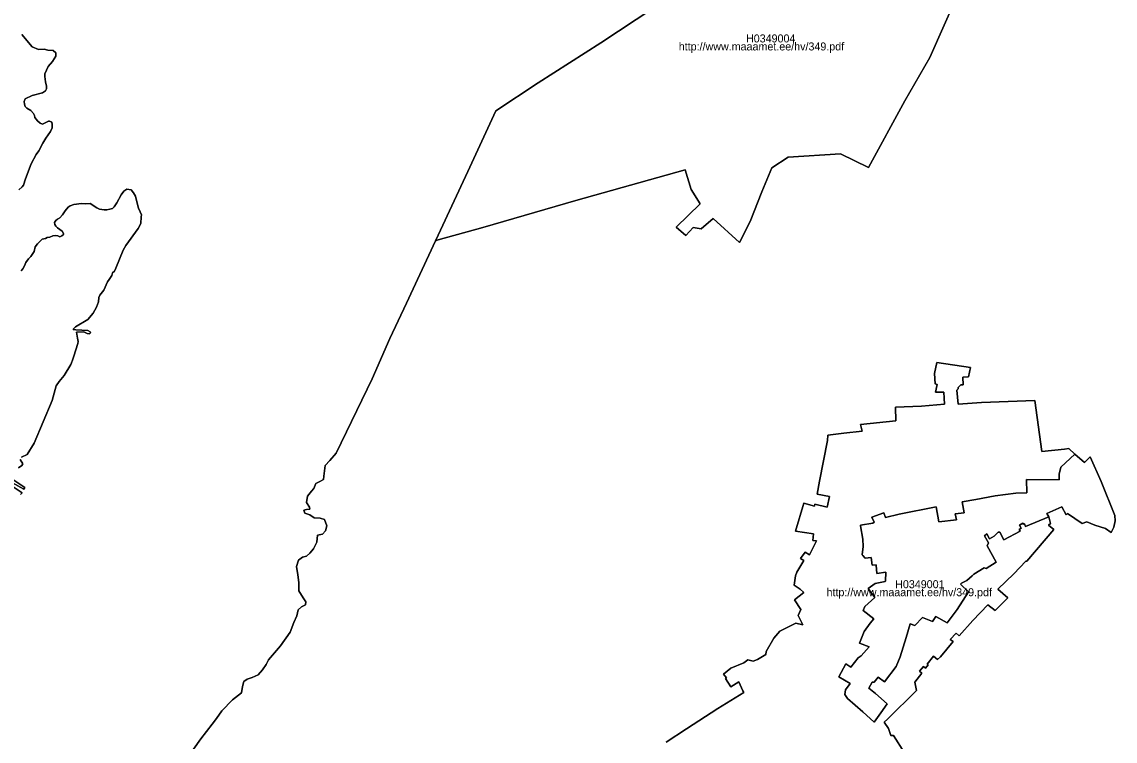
# Model space of a CAD drawing. Extents: x 369010 to 739155, y 6377141 to 6634081.
# Drawn here: x 408268 to 411682, y 6457361 to 6459609 of the extents above; entities that cross this region are included whole.
import ezdxf

# ---------------------------------------------------------------- set-up
doc = ezdxf.new("R2010")
doc.units = 0
for name, color, linetype in [('H_LINK', 7, 'Continuous'), ('H_PIIR', 7, 'Continuous'), ('H_TUNNUS', 7, 'Continuous')]:
    doc.layers.add(name, color=color, linetype=linetype)

msp = doc.modelspace()

# ---------------------------------------------------------------- linework, layer by layer
at = {"layer": 'H_PIIR'}
for points in [[(410406.5801, 6459763.3447), (410075.63, 6459543.3546), (409879.88, 6459418.1246), (409748, 6459331.1447), (409660.4299, 6459141.0446), (409567.4599, 6458942.0746), (409559.4256, 6458924.7699), (409468.9101, 6458729.8146), (409417.27, 6458619.5746), (409361.2, 6458493.5847), (409249.6301, 6458260.8146), (409229.16, 6458237.7446), (409215.22, 6458222.0646), (409210.8699, 6458188.9846), (409209.56, 6458178.9747), (409197.88, 6458172.2546), (409186.1199, 6458166.1546), (409179.59, 6458150.4846), (409171.7501, 6458141.7746), (409159.5499, 6458126.1046), (409156.5, 6458106.9547), (409165.65, 6458092.1446), (409167.39, 6458085.6147), (409156.5, 6458084.7446), (409147.86, 6458082.2746), (409150.9099, 6458073.1346), (409167.46, 6458068.3447), (409180.09, 6458058.3347), (409199.69, 6458057.4646), (409212.32, 6458053.9746), (409219.7201, 6458033.9546), (409215.8, 6458018.2846), (409206.22, 6458007.3946), (409190.98, 6458004.7847), (409188.3599, 6457983.0146), (409177.9799, 6457961.5047), (409167.0999, 6457948.0046), (409156.6399, 6457938.4247), (409144.0099, 6457935.8146), (409131.3801, 6457926.6746), (409125.72, 6457906.2147), (409129.21, 6457880.9646), (409132.26, 6457856.3146), (409132.26, 6457830.1946), (409146.19, 6457808.8646), (409154.4701, 6457796.4547), (409153.1599, 6457786.4446), (409140.5299, 6457780.3447), (409130.0799, 6457771.6447), (409126.1601, 6457752.4846), (409117.4499, 6457731.5946), (409105.25, 6457701.5546), (409075.4001, 6457658.7446), (409037.8299, 6457614.7447), (409030.2, 6457600.0946), (409018.8099, 6457583.8746), (409005.22, 6457567.6646), (408986.9, 6457559.4247), (408971.5601, 6457554.1647), (408961.0399, 6457547.5946), (408956.65, 6457531.3746), (408953.25, 6457512.1746), (408944.4801, 6457504.7246), (408925.19, 6457490.2546), (408892.4199, 6457455.7546), (408875.32, 6457431.2147), (408861.73, 6457414.1246), (408826.44, 6457367.8147), (408803.21, 6457335.3847)], [(411197.3, 6459709.72), (411103.07, 6459497.49), (411025.15, 6459361.86), (410911.8699, 6459153.23), (410824.0899, 6459196.29), (410660.8, 6459185.7701), (410609.77, 6459152.2701), (410579.15, 6459077.62), (410542.41, 6458984.7899), (410508.87, 6458918.81), (410427.2199, 6458994.42), (410389.46, 6458961.8801), (410363.94, 6458965.71), (410341.49, 6458940.83), (410310.87, 6458966.67), (410386.47, 6459040.2199), (410358.19, 6459084.6699), (410339.4599, 6459146.68), (409997.68, 6459050.86), (409707.46, 6458966.09), (409568.0599, 6458927.1799), (409559.4256, 6458924.7699), (409567.4599, 6458942.0746), (409660.4299, 6459141.0446), (409748, 6459331.1447), (409879.88, 6459418.1246), (410075.63, 6459543.3546), (410406.5801, 6459763.3447)], [(408803.21, 6457335.3847), (408826.44, 6457367.8147), (408861.73, 6457414.1246), (408875.32, 6457431.2147), (408892.4199, 6457455.7546), (408925.19, 6457490.2546), (408944.4801, 6457504.7246), (408953.25, 6457512.1746), (408956.65, 6457531.3746), (408961.0399, 6457547.5946), (408971.5601, 6457554.1647), (408986.9, 6457559.4247), (409005.22, 6457567.6646), (409018.8099, 6457583.8746), (409030.2, 6457600.0946), (409037.8299, 6457614.7447), (409075.4001, 6457658.7446), (409105.25, 6457701.5546), (409117.4499, 6457731.5946), (409126.1601, 6457752.4846), (409130.0799, 6457771.6447), (409140.5299, 6457780.3447), (409153.1599, 6457786.4446), (409154.4701, 6457796.4547), (409146.19, 6457808.8646), (409132.26, 6457830.1946), (409132.26, 6457856.3146), (409129.21, 6457880.9646), (409125.72, 6457906.2147), (409131.3801, 6457926.6746), (409144.0099, 6457935.8146), (409156.6399, 6457938.4247), (409167.0999, 6457948.0046), (409177.9799, 6457961.5047), (409188.3599, 6457983.0146), (409190.98, 6458004.7847), (409206.22, 6458007.3946), (409215.8, 6458018.2846), (409219.7201, 6458033.9546), (409212.32, 6458053.9746), (409199.69, 6458057.4646), (409180.09, 6458058.3347), (409167.46, 6458068.3447), (409150.9099, 6458073.1346), (409147.86, 6458082.2746), (409156.5, 6458084.7446), (409167.39, 6458085.6147), (409165.65, 6458092.1446), (409156.5, 6458106.9547), (409159.5499, 6458126.1046), (409171.7501, 6458141.7746), (409179.59, 6458150.4846), (409186.1199, 6458166.1546), (409197.88, 6458172.2546), (409209.56, 6458178.9747), (409210.8699, 6458188.9846), (409215.22, 6458222.0646), (409229.16, 6458237.7446), (409249.6301, 6458260.8146), (409361.2, 6458493.5847), (409417.27, 6458619.5746), (409468.9101, 6458729.8146), (409559.4256, 6458924.7699), (409568.0599, 6458927.1799), (409707.46, 6458966.09), (409997.68, 6459050.86), (410339.4599, 6459146.68), (410358.19, 6459084.6699), (410386.47, 6459040.2199), (410310.87, 6458966.67), (410341.49, 6458940.83), (410363.94, 6458965.71), (410389.46, 6458961.8801), (410427.2199, 6458994.42), (410508.87, 6458918.81), (410542.41, 6458984.7899), (410579.15, 6459077.62), (410609.77, 6459152.2701), (410660.8, 6459185.7701), (410824.0899, 6459196.29), (410911.8699, 6459153.23), (411025.15, 6459361.86), (411103.07, 6459497.49), (411197.3, 6459709.72)], [(408258.3099, 6459083.87), (408268.6399, 6459092.7199), (408272.3301, 6459097.8799), (408278.98, 6459118.52), (408296.69, 6459165.25), (408312.18, 6459194), (408320.3, 6459205.7899), (408332.8501, 6459229.38), (408342.42, 6459245.1401), (408357.2, 6459266.5301), (408362.37, 6459277.59), (408362.37, 6459287.9101), (408360.89, 6459295.2799), (408354.2501, 6459298.2301), (408350.56, 6459298.2301), (408332.1099, 6459288.65), (408324.7301, 6459292.3299), (408316.6099, 6459299.71), (408308.4899, 6459310.03), (408307.02, 6459315.92), (408304.0701, 6459322.56), (408295.9501, 6459332.1399), (408283.4, 6459338.78), (408278.24, 6459344.67), (408275.29, 6459351.3101), (408274.5501, 6459359.4201), (408278.24, 6459368.26), (408299.64, 6459378.14), (408332.1099, 6459386.9799), (408340.9701, 6459392.8801), (408344.66, 6459399.51), (408344.66, 6459407.62), (408341.7, 6459421.6299), (408339.49, 6459437.8501), (408339.49, 6459446.69), (408349.82, 6459468.81), (408363.17, 6459484.86), (408373.63, 6459501.12), (408373.1899, 6459511.97), (408365.39, 6459519.1299), (408348.8999, 6459519.7801), (408336.98, 6459523.47), (408318.9701, 6459522.6099), (408300.11, 6459530.42), (408267.19, 6459568.93)], [(408267.19, 6459568.93), (408300.11, 6459530.42), (408318.9701, 6459522.6099), (408336.98, 6459523.47), (408348.8999, 6459519.7801), (408365.39, 6459519.1299), (408373.1899, 6459511.97), (408373.63, 6459501.12), (408363.17, 6459484.86), (408349.82, 6459468.81), (408339.49, 6459446.69), (408339.49, 6459437.8501), (408341.7, 6459421.6299), (408344.66, 6459407.62), (408344.66, 6459399.51), (408340.9701, 6459392.8801), (408332.1099, 6459386.9799), (408299.64, 6459378.14), (408278.24, 6459368.26), (408274.5501, 6459359.4201), (408275.29, 6459351.3101), (408278.24, 6459344.67), (408283.4, 6459338.78), (408295.9501, 6459332.1399), (408304.0701, 6459322.56), (408307.02, 6459315.92), (408308.4899, 6459310.03), (408316.6099, 6459299.71), (408324.7301, 6459292.3299), (408332.1099, 6459288.65), (408350.56, 6459298.2301), (408354.2501, 6459298.2301), (408360.89, 6459295.2799), (408362.37, 6459287.9101), (408362.37, 6459277.59), (408357.2, 6459266.5301), (408342.42, 6459245.1401), (408332.8501, 6459229.38), (408320.3, 6459205.7899), (408312.18, 6459194), (408296.69, 6459165.25), (408278.98, 6459118.52), (408272.3301, 6459097.8799), (408268.6399, 6459092.7199), (408258.3099, 6459083.87)], [(408266.14, 6458248.28), (408284.3601, 6458256.0999), (408305.53, 6458291.52), (408362.36, 6458425.64), (408374.8799, 6458470.9201), (408383.99, 6458484.38), (408399.1701, 6458503.48), (408420.2, 6458537.61), (408422.3201, 6458543.0101), (408425.47, 6458550.9999), (408429.5, 6458563.88), (408442.72, 6458603.08), (408443.87, 6458609.7899), (408441.7599, 6458620.37), (408438.0443, 6458639.0012), (408461.32, 6458639.73), (408471.8499, 6458634.35), (408478.37, 6458633.5801), (408482.01, 6458636.4601), (408480.4799, 6458639.9201), (408473.2, 6458644.22), (408436.5813, 6458646.3368), (408427.5301, 6458646.8601), (408428.5099, 6458649.83), (408434.9299, 6458655.76), (408473.95, 6458678.4899), (408489.7501, 6458698.2501), (408501.11, 6458717.52), (408506.5401, 6458733.3299), (408507.5, 6458747.42), (408511.46, 6458754.83), (408523.8001, 6458770.1399), (408534.6699, 6458795.84), (408540.5901, 6458803.2501), (408548.4999, 6458816.1), (408550.47, 6458824.5001), (408556.4, 6458829.93), (408561.3401, 6458838.8299), (408584.05, 6458895.65), (408591.9501, 6458909.9801), (408630.4799, 6458962.85), (408639.37, 6458978.6601), (408640.3901, 6458999.57), (408640.8799, 6459005.1501), (408637.19, 6459015.4699), (408632.02, 6459026.5301), (408628.3301, 6459037.58), (408622.4299, 6459064.12), (408616.53, 6459074.4401), (408609.1499, 6459083.29), (408595.12, 6459086.24), (408586.27, 6459079.6001), (408577.4099, 6459068.5499), (408564.1299, 6459043.48), (408556.0099, 6459030.9499), (408550.11, 6459025.05), (408542.7299, 6459022.84), (408532.3999, 6459021.37), (408524.2799, 6459021.37), (408509.9601, 6459023.5801), (408501.8399, 6459027.26), (408480.4399, 6459040.53), (408466.42, 6459039.8001), (408453.8799, 6459040.53), (408430.2599, 6459037.58), (408418.45, 6459033.8999), (408412.55, 6459029.48), (408402.96, 6459018.4201), (408394.1, 6459005.89), (408385.9801, 6458996.3), (408378.6, 6458991.8801), (408373.44, 6458987.46), (408369.01, 6458981.56), (408370.48, 6458975.6599), (408373.44, 6458970.5001), (408378.6, 6458964.5999), (408393.3599, 6458955.02), (408397.05, 6458947.65), (408397.05, 6458943.9601), (408392.62, 6458939.54), (408385.9801, 6458936.59), (408379.34, 6458940.28), (408373.44, 6458941.0199), (408363.84, 6458939.54), (408354.99, 6458935.8601), (408346.1301, 6458935.12), (408340.9701, 6458931.43), (408330.63, 6458929.22), (408315.87, 6458914.4799), (408309.2301, 6458905.63), (408305.54, 6458890.8901), (408295.2099, 6458875.41), (408288.57, 6458868.04), (408279.7099, 6458856.2401), (408276.02, 6458846.66), (408270.86, 6458837.0799), (408265.69, 6458830.44)], [(408265.69, 6458830.44), (408270.86, 6458837.0799), (408276.02, 6458846.66), (408279.7099, 6458856.2401), (408288.57, 6458868.04), (408295.2099, 6458875.41), (408305.54, 6458890.8901), (408309.2301, 6458905.63), (408315.87, 6458914.4799), (408330.63, 6458929.22), (408340.9701, 6458931.43), (408346.1301, 6458935.12), (408354.99, 6458935.8601), (408363.84, 6458939.54), (408373.44, 6458941.0199), (408379.34, 6458940.28), (408385.9801, 6458936.59), (408392.62, 6458939.54), (408397.05, 6458943.9601), (408397.05, 6458947.65), (408393.3599, 6458955.02), (408378.6, 6458964.5999), (408373.44, 6458970.5001), (408370.48, 6458975.6599), (408369.01, 6458981.56), (408373.44, 6458987.46), (408378.6, 6458991.8801), (408385.9801, 6458996.3), (408394.1, 6459005.89), (408402.96, 6459018.4201), (408412.55, 6459029.48), (408418.45, 6459033.8999), (408430.2599, 6459037.58), (408453.8799, 6459040.53), (408466.42, 6459039.8001), (408480.4399, 6459040.53), (408501.8399, 6459027.26), (408509.9601, 6459023.5801), (408524.2799, 6459021.37), (408532.3999, 6459021.37), (408542.7299, 6459022.84), (408550.11, 6459025.05), (408556.0099, 6459030.9499), (408564.1299, 6459043.48), (408577.4099, 6459068.5499), (408586.27, 6459079.6001), (408595.12, 6459086.24), (408609.1499, 6459083.29), (408616.53, 6459074.4401), (408622.4299, 6459064.12), (408628.3301, 6459037.58), (408632.02, 6459026.5301), (408637.19, 6459015.4699), (408640.8799, 6459005.1501), (408640.3901, 6458999.57), (408639.37, 6458978.6601), (408630.4799, 6458962.85), (408591.9501, 6458909.9801), (408584.05, 6458895.65), (408561.3401, 6458838.8299), (408556.4, 6458829.93), (408550.47, 6458824.5001), (408548.4999, 6458816.1), (408540.5901, 6458803.2501), (408534.6699, 6458795.84), (408523.8001, 6458770.1399), (408511.46, 6458754.83), (408507.5, 6458747.42), (408506.5401, 6458733.3299), (408501.11, 6458717.52), (408489.7501, 6458698.2501), (408473.95, 6458678.4899), (408434.9299, 6458655.76), (408428.5099, 6458649.83), (408427.5301, 6458646.8601), (408436.5813, 6458646.3368), (408473.2, 6458644.22), (408480.4799, 6458639.9201), (408482.01, 6458636.4601), (408478.37, 6458633.5801), (408471.8499, 6458634.35), (408461.32, 6458639.73), (408438.0443, 6458639.0012), (408441.7599, 6458620.37), (408443.87, 6458609.7899), (408442.72, 6458603.08), (408429.5, 6458563.88), (408425.47, 6458550.9999), (408422.3201, 6458543.0101), (408420.2, 6458537.61), (408399.1701, 6458503.48), (408383.99, 6458484.38), (408374.8799, 6458470.9201), (408362.36, 6458425.64), (408305.53, 6458291.52), (408284.3601, 6458256.0999), (408266.14, 6458248.28)], [(411024.75, 6457323.99), (410989.9001, 6457378.37), (410982.15, 6457377.9899), (410974.41, 6457399.9701), (410961.16, 6457419.85), (410970.93, 6457429.59), (411061.8299, 6457519.19), (411056.55, 6457545.62), (411079.01, 6457572.71), (411071.7401, 6457579.3199), (411083.64, 6457593.8501), (411090.2501, 6457588.5699), (411098.1699, 6457599.14), (411095.06, 6457601.44), (411115.3, 6457626.6799), (411127.1199, 6457616.16), (411136.8499, 6457624.05), (411176.6999, 6457671.7501), (411167.24, 6457678.5899), (411185.3699, 6457698.04), (411195.36, 6457690.41), (411238.06, 6457737.3599), (411284.7201, 6457786.9799), (411308.05, 6457769.01), (411346.8, 6457808.85), (411315.55, 6457836.2001), (411365.4801, 6457883.59), (411402.8599, 6457923.3201), (411406.3699, 6457923.3201), (411491.05, 6458022.64), (411474.12, 6458035.49), (411479.96, 6458041.33), (411474.82, 6458061.33), (411468.99, 6458072.6599), (411515.65, 6458092.58), (411529.3901, 6458068.36), (411533.14, 6458072.27), (411579.8, 6458041.0101), (411593.55, 6458045.7), (411619.3801, 6458035.54), (411652.7099, 6458025.3901), (411669.3799, 6458012.89), (411678.1199, 6458029.29), (411682.2901, 6458049.22), (411681.46, 6458066.02), (411638.61, 6458171.79), (411604.44, 6458249.1399), (411586.53, 6458231.17), (411556.53, 6458257.74), (411537.62, 6458275.2301), (411523.82, 6458273.3799), (411453.1801, 6458265.9901), (411431.1599, 6458425.8801), (411265.0301, 6458418.71), (411191.6, 6458414.3801), (411188.3101, 6458457.5099), (411192.2599, 6458461.5199), (411192.2599, 6458465.5199), (411200.14, 6458474.1499), (411207.3701, 6458474.7699), (411206.7099, 6458498.4899), (411224.45, 6458499.41), (411231.0201, 6458528.37), (411124.9001, 6458544.0399), (411118.0001, 6458509.5401), (411119.6501, 6458477.1901), (411126.22, 6458475.65), (411121.62, 6458451.62), (411147.2399, 6458451.62), (411149.5399, 6458413.42), (411077.96, 6458407.8699), (410996.48, 6458404.3699), (410997.46, 6458361.59), (410887.2201, 6458350.37), (410891.8201, 6458329.72), (410834.5799, 6458323.1601), (410785.28, 6458317.13), (410783.8501, 6458299.9799), (410758.9299, 6458172.8), (410751.7, 6458132.44), (410790.47, 6458125.6599), (410782.5899, 6458091.7701), (410744.14, 6458101.6301), (410742.8299, 6458095.1599), (410709.65, 6458104.1), (410684.0501, 6458016.8001), (410740.5701, 6458008.48), (410737.94, 6457987.8399), (410749.1099, 6457986.91), (410728.08, 6457943.4701), (410713.62, 6457951.17), (410699.17, 6457931.77), (410710.34, 6457925.3), (410687.67, 6457889.38), (410683.73, 6457877.6801), (410679.79, 6457847.79), (410698.5101, 6457836.0899), (410709.69, 6457824.99), (410680.77, 6457801.89), (410700.49, 6457772.31), (410692.29, 6457753.0701), (410706.74, 6457724.7199), (410685.0599, 6457729.65), (410635.12, 6457705), (410616.3899, 6457682.82), (410592.52, 6457640.73), (410591.54, 6457631.49), (410565.2501, 6457615.7701), (410551.45, 6457610.84), (410535.35, 6457614.5399), (410522.5401, 6457605.61), (410481.4699, 6457589.2801), (410459.4599, 6457569.87), (410468.66, 6457558.78), (410465.7, 6457556.3101), (410482.46, 6457530.13), (410507.4299, 6457545.8399), (410519.5801, 6457518.1099), (410522.5401, 6457512.5601), (410441.43, 6457463.1), (410343.6301, 6457399.08), (410279.6101, 6457357.8401)], [(410279.6101, 6457357.8401), (410343.6301, 6457399.08), (410441.43, 6457463.1), (410522.5401, 6457512.5601), (410519.5801, 6457518.1099), (410507.4299, 6457545.8399), (410482.46, 6457530.13), (410465.7, 6457556.3101), (410468.66, 6457558.78), (410459.4599, 6457569.87), (410481.4699, 6457589.2801), (410522.5401, 6457605.61), (410535.35, 6457614.5399), (410551.45, 6457610.84), (410565.2501, 6457615.7701), (410591.54, 6457631.49), (410592.52, 6457640.73), (410616.3899, 6457682.82), (410635.12, 6457705), (410685.0599, 6457729.65), (410706.74, 6457724.7199), (410692.29, 6457753.0701), (410700.49, 6457772.31), (410680.77, 6457801.89), (410709.69, 6457824.99), (410698.5101, 6457836.0899), (410679.79, 6457847.79), (410683.73, 6457877.6801), (410687.67, 6457889.38), (410710.34, 6457925.3), (410699.17, 6457931.77), (410713.62, 6457951.17), (410728.08, 6457943.4701), (410749.1099, 6457986.91), (410737.94, 6457987.8399), (410740.5701, 6458008.48), (410684.0501, 6458016.8001), (410709.65, 6458104.1), (410742.8299, 6458095.1599), (410744.14, 6458101.6301), (410782.5899, 6458091.7701), (410790.47, 6458125.6599), (410751.7, 6458132.44), (410758.9299, 6458172.8), (410783.8501, 6458299.9799), (410785.28, 6458317.13), (410834.5799, 6458323.1601), (410891.8201, 6458329.72), (410887.2201, 6458350.37), (410997.46, 6458361.59), (410996.48, 6458404.3699), (411077.96, 6458407.8699), (411149.5399, 6458413.42), (411147.2399, 6458451.62), (411121.62, 6458451.62), (411126.22, 6458475.65), (411119.6501, 6458477.1901), (411118.0001, 6458509.5401), (411124.9001, 6458544.0399), (411231.0201, 6458528.37), (411224.45, 6458499.41), (411206.7099, 6458498.4899), (411207.3701, 6458474.7699), (411200.14, 6458474.1499), (411192.2599, 6458465.5199), (411192.2599, 6458461.5199), (411188.3101, 6458457.5099), (411191.6, 6458414.3801), (411265.0301, 6458418.71), (411431.1599, 6458425.8801), (411453.1801, 6458265.9901), (411523.82, 6458273.3799), (411537.62, 6458275.2301), (411556.53, 6458257.74), (411512.37, 6458216.72), (411507.79, 6458195.23), (411507.49, 6458177.0299), (411405.42, 6458178.59), (411406.26, 6458137.18), (411371.7901, 6458136.01), (411308.04, 6458127.0201), (411247.27, 6458116.16), (411204.78, 6458108.74), (411210.61, 6458074.3599), (411183.1201, 6458070.8399), (411186.4499, 6458052.4799), (411131.87, 6458045.84), (411123.54, 6458092.72), (411007.48, 6458069.62), (410965.4, 6458059.86), (410959.57, 6458073.9201), (410922.07, 6458061.0299), (410929.57, 6458044.62), (410925.41, 6458042.28), (410886.66, 6458036.03), (410886.9899, 6458033.9699), (410893.74, 6457992.27), (410895.41, 6457968.99), (410892.08, 6457942.8199), (410893.74, 6457941.0499), (410901.24, 6457933.0499), (410920.41, 6457935), (410920.4899, 6457934.35), (410923.3999, 6457910.4), (410935.4, 6457911.95), (410935.6501, 6457909.26), (410937.8299, 6457885.7601), (410937.9001, 6457885), (410966.2301, 6457888.51), (410965.4, 6457860.3901), (410964.16, 6457860.14), (410932.49, 6457853.75), (410910.47, 6457837.54), (410932.1401, 6457809.81), (410900.02, 6457781.19), (410895.47, 6457769.1799), (410928.8, 6457742.6099), (410917.1401, 6457729.3299), (410898.39, 6457703.55), (410883.39, 6457666.83), (410914.2401, 6457655.66), (410889.25, 6457627.54), (410879.25, 6457620.8999), (410856.75, 6457592.38), (410841.34, 6457602.14), (410819.6701, 6457561.91), (410855.08, 6457541.1999), (410839.6699, 6457521.28), (410837.5901, 6457506.82), (410846.7501, 6457494.32), (410893.83, 6457452.5201), (410929.2401, 6457419.71), (410950.38, 6457449.6401), (410970.0699, 6457477.52), (410934.2, 6457509.4899), (410912.74, 6457525.97), (410923.78, 6457544.7399), (410929.3001, 6457544.7399), (410941.9901, 6457560.75), (410961.67, 6457546.4599), (410998.27, 6457594.5), (411010.35, 6457624.58), (411029.1001, 6457684.74), (411041.9, 6457727.6499), (411056.9, 6457722.5701), (411081.0601, 6457747.1799), (411111.89, 6457734.29), (411121.8899, 6457750.6899), (411157.7201, 6457730.77), (411188.9001, 6457772.1301), (411224.31, 6457827.15), (411199.2199, 6457851), (411202.43, 6457854.1101), (411218.9001, 6457863.1699), (411235.6801, 6457877.44), (411240.56, 6457882.3001), (411273.48, 6457902.22), (411279.72, 6457899.88), (411310.42, 6457919.99), (411282.51, 6457971.55), (411286.68, 6457980.9299), (411274.1799, 6458002.8099), (411281.2601, 6458008.28), (411289.59, 6457993.43), (411304.59, 6458001.2401), (411317.09, 6458013.7399), (411322.51, 6458013.7399), (411334.1699, 6457990.3001), (411385.83, 6458016.87), (411382.0799, 6458022.73), (411389.1601, 6458026.25), (411383.3301, 6458036.01), (411394.1599, 6458041.87), (411395.83, 6458038.7501), (411399.16, 6458040.3099), (411401.91, 6458031.6399), (411474.82, 6458061.33), (411479.96, 6458041.33), (411474.12, 6458035.49), (411491.05, 6458022.64), (411406.3699, 6457923.3201), (411402.8599, 6457923.3201), (411365.4801, 6457883.59), (411315.55, 6457836.2001), (411346.8, 6457808.85), (411308.05, 6457769.01), (411284.7201, 6457786.9799), (411238.06, 6457737.3599), (411195.36, 6457690.41), (411185.3699, 6457698.04), (411167.24, 6457678.5899), (411176.6999, 6457671.7501), (411136.8499, 6457624.05), (411127.1199, 6457616.16), (411115.3, 6457626.6799), (411095.06, 6457601.44), (411098.1699, 6457599.14), (411090.2501, 6457588.5699), (411083.64, 6457593.8501), (411071.7401, 6457579.3199), (411079.01, 6457572.71), (411056.55, 6457545.62), (411061.8299, 6457519.19), (410970.93, 6457429.59), (410961.16, 6457419.85), (410974.41, 6457399.9701), (410982.15, 6457377.9899), (410989.9001, 6457378.37), (411024.75, 6457323.99)], [(408257.03, 6458215.3001), (408267.88, 6458222.6699), (408270.92, 6458227.8799), (408262.24, 6458240.9)], [(408262.24, 6458240.9), (408270.92, 6458227.8799), (408267.88, 6458222.6699), (408257.03, 6458215.3001)], [(408237.95, 6458167.9801), (408273.52, 6458148.02), (408276.99, 6458153.22), (408235.7799, 6458181)], [(408235.7799, 6458181), (408276.99, 6458153.22), (408273.52, 6458148.02), (408237.95, 6458167.9801)], [(408263.5399, 6458131.5199), (408268.7499, 6458136.7299), (408234.48, 6458159.3001)], [(408234.48, 6458159.3001), (408268.7499, 6458136.7299), (408263.5399, 6458131.5199)]]:
    msp.add_lwpolyline(points, dxfattribs=at)
msp.add_lwpolyline([(411556.53, 6458257.74), (411586.53, 6458231.17), (411604.44, 6458249.1399), (411638.61, 6458171.79), (411681.46, 6458066.02), (411682.2901, 6458049.22), (411678.1199, 6458029.29), (411669.3799, 6458012.89), (411652.7099, 6458025.3901), (411619.3801, 6458035.54), (411593.55, 6458045.7), (411579.8, 6458041.0101), (411533.14, 6458072.27), (411529.3901, 6458068.36), (411515.65, 6458092.58), (411468.99, 6458072.6599), (411474.82, 6458061.33), (411401.91, 6458031.6399), (411399.16, 6458040.3099), (411395.83, 6458038.7501), (411394.1599, 6458041.87), (411383.3301, 6458036.01), (411389.1601, 6458026.25), (411382.0799, 6458022.73), (411385.83, 6458016.87), (411334.1699, 6457990.3001), (411322.51, 6458013.7399), (411317.09, 6458013.7399), (411304.59, 6458001.2401), (411289.59, 6457993.43), (411281.2601, 6458008.28), (411274.1799, 6458002.8099), (411286.68, 6457980.9299), (411282.51, 6457971.55), (411310.42, 6457919.99), (411279.72, 6457899.88), (411273.48, 6457902.22), (411240.56, 6457882.3001), (411235.6801, 6457877.44), (411218.9001, 6457863.1699), (411202.43, 6457854.1101), (411199.2199, 6457851), (411224.31, 6457827.15), (411188.9001, 6457772.1301), (411157.7201, 6457730.77), (411121.8899, 6457750.6899), (411111.89, 6457734.29), (411081.0601, 6457747.1799), (411056.9, 6457722.5701), (411041.9, 6457727.6499), (411029.1001, 6457684.74), (411010.35, 6457624.58), (410998.27, 6457594.5), (410961.67, 6457546.4599), (410941.9901, 6457560.75), (410929.3001, 6457544.7399), (410923.78, 6457544.7399), (410912.74, 6457525.97), (410934.2, 6457509.4899), (410970.0699, 6457477.52), (410950.38, 6457449.6401), (410929.2401, 6457419.71), (410893.83, 6457452.5201), (410846.7501, 6457494.32), (410837.5901, 6457506.82), (410839.6699, 6457521.28), (410855.08, 6457541.1999), (410819.6701, 6457561.91), (410841.34, 6457602.14), (410856.75, 6457592.38), (410879.25, 6457620.8999), (410889.25, 6457627.54), (410914.2401, 6457655.66), (410883.39, 6457666.83), (410898.39, 6457703.55), (410917.1401, 6457729.3299), (410928.8, 6457742.6099), (410895.47, 6457769.1799), (410900.02, 6457781.19), (410932.1401, 6457809.81), (410910.47, 6457837.54), (410932.49, 6457853.75), (410964.16, 6457860.14), (410965.4, 6457860.3901), (410966.2301, 6457888.51), (410937.9001, 6457885), (410937.8299, 6457885.7601), (410935.6501, 6457909.26), (410935.4, 6457911.95), (410923.3999, 6457910.4), (410920.4899, 6457934.35), (410920.41, 6457935), (410901.24, 6457933.0499), (410893.74, 6457941.0499), (410892.08, 6457942.8199), (410895.41, 6457968.99), (410893.74, 6457992.27), (410886.9899, 6458033.9699), (410886.66, 6458036.03), (410925.41, 6458042.28), (410929.57, 6458044.62), (410922.07, 6458061.0299), (410959.57, 6458073.9201), (410965.4, 6458059.86), (411007.48, 6458069.62), (411123.54, 6458092.72), (411131.87, 6458045.84), (411186.4499, 6458052.4799), (411183.1201, 6458070.8399), (411210.61, 6458074.3599), (411204.78, 6458108.74), (411247.27, 6458116.16), (411308.04, 6458127.0201), (411371.7901, 6458136.01), (411406.26, 6458137.18), (411405.42, 6458178.59), (411507.49, 6458177.0299), (411507.79, 6458195.23), (411512.37, 6458216.72)], close=True, dxfattribs=at)

# ---------------------------------------------------------------- texts
at = {"layer": 'H_LINK'}
msp.add_text('http://www.maaamet.ee/hv/349.pdf', height=25, rotation=360, dxfattribs=at).set_placement((410319.3431, 6459519.4173))
msp.add_text('http://www.maaamet.ee/hv/349.pdf', height=25, dxfattribs=at).set_placement((410780.8824, 6457813.725))
at = {"layer": 'H_TUNNUS'}
msp.add_text('H0349004', height=25, rotation=360, dxfattribs=at).set_placement((410529.3224, 6459544.4173))
msp.add_text('H0349001', height=25, dxfattribs=at).set_placement((410995.2363, 6457838.725))

doc.saveas('drawing.dxf')
